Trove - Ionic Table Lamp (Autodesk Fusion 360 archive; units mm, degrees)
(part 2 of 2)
design "Balon v2"
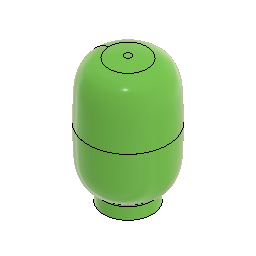
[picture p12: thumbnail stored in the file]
derived_base_feature "Derived Base Feature" bodies "Balon"
work_plane "WorkPlane1" AlongDistance 0
sketch "Sketch1" plane through (0, 0, 0) normal (0, 1, 0) x axis (1, 0, 0)
  line L1 (0, 317.5) -> (0, 2.9083)
  curve K1 (-82.9821, 124.2212) -> (-50.8, 237.8015)
  curve K2 (-51.0925, 237.681) -> (-50.8, 237.8015)
  curve K3 (-51.3855, 237.5558) -> (-51.0925, 237.681)
  curve K4 (-54.7608, 236.0513) -> (-51.3855, 237.5558)
  curve K5 (-57.9615, 234.05) -> (-54.7608, 236.0513)
  curve K6 (-67.2727, 226.749) -> (-57.9615, 234.05)
  curve K7 (-69.0552, 224.2615) -> (-67.2727, 226.749)
  curve K8 (-72.1872, 218.7832) -> (-69.0552, 224.2615)
  curve K9 (-74.1213, 215.1556) -> (-72.1872, 218.7832)
  curve K10 (-78.3031, 204.3965) -> (-74.1213, 215.1556)
  curve K11 (-79.7275, 197.3397) -> (-78.3031, 204.3965)
  curve K12 (-81.3333, 185.4664) -> (-79.7275, 197.3397)
  curve K13 (-81.6254, 178.4008) -> (-81.3333, 185.4664)
  curve K14 (-82.49, 152.2133) -> (-81.6254, 178.4008)
  curve K15 (-82.9821, 136.067) -> (-82.49, 152.2133)
  curve K16 (-82.9821, 124.2212) -> (-82.9821, 136.067)
  curve K17 (50.8, 237.7999) -> (82.9821, 124.2212)
  curve K18 (82.9821, 140.3031) -> (82.9821, 124.2212)
  curve K19 (81.9353, 169.4257) -> (82.9821, 140.3031)
  curve K20 (81.3621, 183.6489) -> (81.9353, 169.4257)
  curve K21 (80.9478, 189.8724) -> (81.3621, 183.6489)
  curve K22 (77.8147, 206.9858) -> (80.9478, 189.8724)
  curve K23 (74.9652, 213.2153) -> (77.8147, 206.9858)
  curve K24 (69.4688, 224.1531) -> (74.9652, 213.2153)
  curve K25 (67.2512, 226.458) -> (69.4688, 224.1531)
  curve K26 (61.5696, 231.3138) -> (67.2512, 226.458)
  curve K27 (57.377, 234.6711) -> (61.5696, 231.3138)
  curve K28 (52.0556, 237.2628) -> (57.377, 234.6711)
  curve K29 (51.4313, 237.5413) -> (52.0556, 237.2628)
  curve K30 (50.8, 237.7999) -> (51.4313, 237.5413)
  line L2 (-50.8, 317.5) -> (-50.8, 237.8015)
  line L3 (50.8, 317.5) -> (50.8, 237.7999)
  line L4 (-19.0713, 6.7501) -> (-19.0713, 6.7501)
  curve K31 (82.9821, 124.1958) -> (40.1509, 7.3012)
  curve K32 (41.8198, 7.6176) -> (40.1509, 7.3012)
  curve K33 (43.2113, 8.0663) -> (41.8198, 7.6176)
  curve K34 (47.0139, 9.2854) -> (43.2113, 8.0663)
  curve K35 (47.3314, 9.3805) -> (47.0139, 9.2854)
  curve K36 (50.1192, 10.3272) -> (47.3314, 9.3805)
  curve K37 (51.833, 11.0085) -> (50.1192, 10.3272)
  curve K38 (57.8313, 14.1895) -> (51.833, 11.0085)
  curve K39 (61.4491, 17.0488) -> (57.8313, 14.1895)
  curve K40 (66.8203, 21.5867) -> (61.4491, 17.0488)
  curve K41 (68.5372, 23.5528) -> (66.8203, 21.5867)
  curve K42 (71.2201, 27.8971) -> (68.5372, 23.5528)
  curve K43 (74.7424, 33.8984) -> (71.2201, 27.8971)
  curve K44 (78.2342, 44.8406) -> (74.7424, 33.8984)
  curve K45 (79.6792, 50.3463) -> (78.2342, 44.8406)
  curve K46 (81.3558, 63.5576) -> (79.6792, 50.3463)
  curve K47 (81.6386, 70.4415) -> (81.3558, 63.5576)
  curve K48 (82.4897, 96.2198) -> (81.6386, 70.4415)
  curve K49 (82.9814, 112.3523) -> (82.4897, 96.2198)
  curve K50 (82.9821, 124.1958) -> (82.9814, 112.3523)
  curve K51 (-40.1501, 7.301) -> (-82.9821, 124.1958)
  curve K52 (-82.9813, 110.5256) -> (-82.9821, 124.1958)
  curve K53 (-82.2545, 88.8594) -> (-82.9813, 110.5256)
  curve K54 (-81.6277, 70.519) -> (-82.2545, 88.8594)
  curve K55 (-81.3572, 64.3441) -> (-81.6277, 70.519)
  curve K56 (-79.4149, 46.8924) -> (-81.3572, 64.3441)
  curve K57 (-76.5204, 38.9768) -> (-79.4149, 46.8924)
  curve K58 (-73.5142, 32.2947) -> (-76.5204, 38.9768)
  curve K59 (-72.5556, 30.3818) -> (-73.5142, 32.2947)
  curve K60 (-69.7914, 25.3691) -> (-72.5556, 30.3818)
  curve K61 (-68.3824, 23.4028) -> (-69.7914, 25.3691)
  curve K62 (-64.5419, 19.5456) -> (-68.3824, 23.4028)
  curve K63 (-62.3002, 17.7646) -> (-64.5419, 19.5456)
  curve K64 (-53.6583, 11.1976) -> (-62.3002, 17.7646)
  curve K65 (-49.6968, 10.1396) -> (-53.6583, 11.1976)
  curve K66 (-43.4141, 8.1331) -> (-49.6968, 10.1396)
  curve K67 (-41.9704, 7.6516) -> (-43.4141, 8.1331)
  curve K68 (-40.1963, 7.3098) -> (-41.9704, 7.6516)
  curve K69 (-40.1732, 7.3054) -> (-40.1963, 7.3098)
  curve K70 (-40.1501, 7.301) -> (-40.1732, 7.3054)
  line L5 (-82.9821, 124.1958) -> (-82.9821, 124.2212)
  line L6 (82.9821, 124.2212) -> (82.9821, 124.1958)
  line L7 (0, 317.5) -> (-50.8, 317.5)
  line L8 (7.2015, 3.048) -> (0, 3.048)
  line L9 (0, 3.048) -> (-7.2015, 3.048)
  arc A1 centre (0, 188.595) radius 185.6867 clockwise from (-7.2015, 3.048) to (-40.1502, 7.301)
  arc A2 centre (0, 188.595) radius 185.6867 clockwise from (40.151, 7.3012) to (7.2015, 3.048)
  point P38 (-40.1502, 7.301)
  point P43 (40.1509, 7.3012)
  point P62 (-40.1501, 7.301)
  point P81 (40.151, 7.3012)
  point P84 (0, 3.048)
  vertical L1
  horizontal L4
  coincident P38 K51
  symmetric L1 A1 A2
  coincident A2 P43
  coincident A1 P62
  coincident K31 P81
  perpendicular L2 L7
  horizontal L8
  coincident L1 P84
  horizontal L9
revolve "Revolve1" sketch "Sketch1" AlongAngle 360
shell "Shell1" innerThickness 3.81
fillet "Fillet1" radius 6.35
offset_faces "OffsetFaces1" distance -50.8
move "Move1"
move "Move2"
component_from_bodies "Body->Comp1"
component_from_bodies "Body->Comp2"
sketch "Sketch2" plane through (0, 0, 0) normal (0, 1, 0) x axis (1, 0, 0)
  line L1 (-85.5221, 124.2212) -> (-85.5221, 124.1961)
  curve K1 (-58.9057, 236.4383) -> (-50.8, 241.7989)
  curve K2 (-50.8, 241.554) -> (-50.8, 241.7989)
  curve K3 (-50.904, 240.933) -> (-50.8, 241.554)
  curve K4 (-51.2936, 240.2837) -> (-50.904, 240.933)
  curve K5 (-51.734, 239.7561) -> (-51.2936, 240.2837)
  curve K6 (-53.328, 238.5038) -> (-51.734, 239.7561)
  curve K7 (-54.0892, 238.1997) -> (-53.328, 238.5038)
  curve K8 (-58.9057, 236.4383) -> (-54.0892, 238.1997)
  curve K9 (-89.3309, 124.2212) -> (-58.9057, 236.4383)
  curve K10 (-62.6336, 234.9735) -> (-58.9057, 236.4383)
  curve K11 (-65.581, 233.1032) -> (-62.6336, 234.9735)
  curve K12 (-73.0224, 227.0019) -> (-65.581, 233.1032)
  curve K13 (-74.8981, 224.836) -> (-73.0224, 227.0019)
  curve K14 (-78.1104, 219.6097) -> (-74.8981, 224.836)
  curve K15 (-80.2663, 215.561) -> (-78.1104, 219.6097)
  curve K16 (-84.0943, 205.8277) -> (-80.2663, 215.561)
  curve K17 (-85.4655, 200.1154) -> (-84.0943, 205.8277)
  curve K18 (-87.4092, 188.5789) -> (-85.4655, 200.1154)
  curve K19 (-87.7349, 182.3889) -> (-87.4092, 188.5789)
  curve K20 (-88.4233, 165.9645) -> (-87.7349, 182.3889)
  curve K21 (-89.328, 138.6964) -> (-88.4233, 165.9645)
  curve K22 (-89.3309, 124.2212) -> (-89.328, 138.6964)
  line L2 (-89.3309, 124.1958) -> (-89.3309, 124.2212)
  curve K23 (-46.5001, 7.301) -> (-89.3309, 124.1958)
  curve K24 (-89.3314, 112.4293) -> (-89.3309, 124.1958)
  curve K25 (-88.8181, 95.3068) -> (-89.3314, 112.4293)
  curve K26 (-88.346, 81.2892) -> (-88.8181, 95.3068)
  curve K27 (-88.0298, 70.4902) -> (-88.346, 81.2892)
  curve K28 (-87.1514, 58.328) -> (-88.0298, 70.4902)
  curve K29 (-86.3326, 50.6119) -> (-87.1514, 58.328)
  curve K30 (-81.0932, 33.6688) -> (-86.3326, 50.6119)
  curve K31 (-77.3163, 27.4309) -> (-81.0932, 33.6688)
  curve K32 (-74.8955, 23.6666) -> (-77.3163, 27.4309)
  curve K33 (-73.5108, 22.0741) -> (-74.8955, 23.6666)
  curve K34 (-70.2346, 19.0457) -> (-73.5108, 22.0741)
  curve K35 (-64.8094, 14.3548) -> (-70.2346, 19.0457)
  curve K36 (-56.6696, 10.3041) -> (-64.8094, 14.3548)
  curve K37 (-54.0053, 9.483) -> (-56.6696, 10.3041)
  curve K38 (-49.1487, 7.9411) -> (-54.0053, 9.483)
  curve K39 (-48.3482, 7.6526) -> (-49.1487, 7.9411)
  curve K40 (-46.5001, 7.301) -> (-48.3482, 7.6526)
  line L3 (0, 266.7) -> (0, 0)
  line L4 (0, 3.048) -> (-7.7894, 3.048)
  line L5 (-50.8, 266.7) -> (-50.8, 241.7989)
  line L6 (0, 266.7) -> (-50.8, 266.7)
  arc A1 centre (-6.9779, 188.7329) radius 185.6867 clockwise from (-7.7894, 3.048) to (-46.5001, 7.301)
  point P1 (0, 0)
  point P44 (0, 0)
  point P46 (0, 3.048)
  point P5 (-50.8, 241.554)
  point P49 (0, 266.7)
  coincident P1 P44
  coincident L3 P46
  coincident P5 L5
  coincident L3 P49
revolve "Revolve2" sketch "Sketch2" AlongAngle 360 bodies "Balon v3"
shell "Shell2" innerThickness 3.81
component_from_bodies "Body->Comp3"
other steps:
base_feature "Base Feature1" bodies "Balon"
base_feature "Base Feature1" bodies "Balon v3"
base_feature "Base Feature1" bodies "Balon v2"
create_component "CreateComponent1"
remove_body "RemoveBody1"
create_component "CreateComponent2"
remove_body "RemoveBody2"
create_component "CreateComponent3"
remove_body "RemoveBody3"
named bodies: "Balon", "Balon v2", "Balon v3"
